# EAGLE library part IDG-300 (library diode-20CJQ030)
InvenSense's IDG-300 Integrated Dual-Axis Gyro Description: The IDG-300 is an integrated dual-axis angular rate sensor (gyroscope). It uses InvenSense?s proprietary and patented MEMS technology with vertically driven, vibrating masses to make a functionally complete, lowcost, dual-axis angular rate sensor. All required electronics are integrated onto a single chip with the sensor. The IDG-300 gyro uses two sensor elements with novel vibrating dual-mass bulk silicon configurations that sense the rate of rotation about the X- and Y-axis (in-plane sensing). This results in a unique, integrated dual-axis gyro with guaranteed-by-design vibration rejection and high cross-axis isolation. It is specifically designed for demanding consumer applications requiring low cost, small size and high performance. The IDG-300 gyro includes integrated electronics necessary for application-ready functionality. It incorporates X- and Y-axis low-pass filters and an EEPROM for on-chip factory calibration of the sensor. Factory trimmed scale factors eliminate the need for external active components and end-user calibration. This product is lead-free and Green Compliant. Features: Integrated X- and Y-axis gyro on a single chip Factory trimmed full scale range of ±500°/sec Integrated low-pass filters Superior vibration rejection over a wide frequency range High cross-axis isolation by design 3V single supply operation 5000 g shock tolerance RoHS compliant (completely lead free) 6 x 6 x 1.5mm QFN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
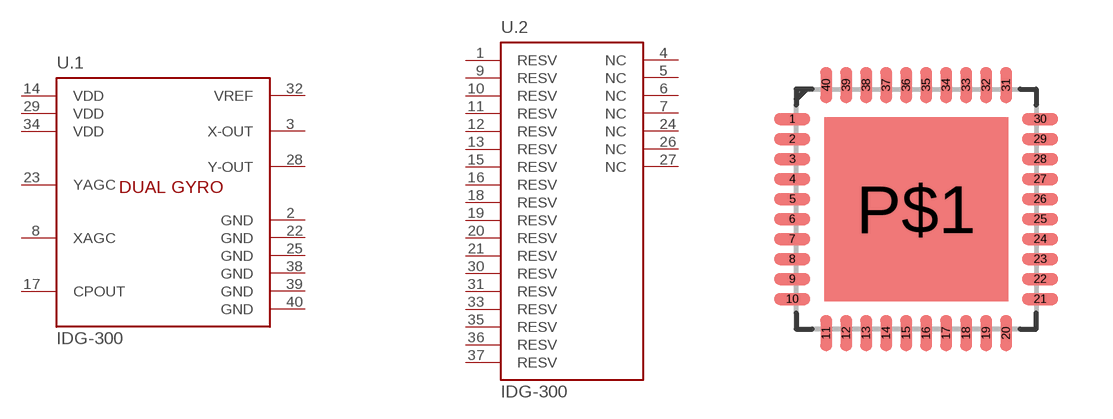
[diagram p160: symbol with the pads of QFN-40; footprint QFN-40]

Designator prefix U; gates .1=IDG-300 .2=IDG-300-NC

## IDG-300  [QFN-40]
1  .2:RESV  pas
2  .1:GND  pwr
3  .1:X-OUT  out
4  .2:NC  nc
5  .2:NC  nc
6  .2:NC  nc
7  .2:NC  nc
8  .1:XAGC  in
9  .2:RESV  pas
10  .2:RESV  pas
11  .2:RESV  pas
12  .2:RESV  pas
13  .2:RESV  pas
14  .1:VDD  pwr
15  .2:RESV  pas
16  .2:RESV  pas
17  .1:CPOUT  out
18  .2:RESV  pas
19  .2:RESV  pas
20  .2:RESV  pas
21  .2:RESV  pas
22  .1:GND  pwr
23  .1:YAGC  in
24  .2:NC  nc
25  .1:GND  pwr
26  .2:NC  nc
27  .2:NC  nc
28  .1:Y-OUT  out
29  .1:VDD  pwr
30  .2:RESV  pas
31  .2:RESV  pas
32  .1:VREF  in
33  .2:RESV  pas
34  .1:VDD  pwr
35  .2:RESV  pas
36  .2:RESV  pas
37  .2:RESV  pas
38  .1:GND  pwr
39  .1:GND  pwr
40  .1:GND  pwr

## Footprint QFN-40 (pad centres in mm)
QFN-40 package use in InvenSense IDG-300
smd 0.9 x 0.3: 1 -3.1,2.25; 2 -3.1,1.75; 3 -3.1,1.25; 4 -3.1,0.75; 5 -3.1,0.25; 6 -3.1,-0.25; 7 -3.1,-0.75; 8 -3.1,-1.25; 9 -3.1,-1.75; 10 -3.1,-2.25; 21 3.1,-2.25; 22 3.1,-1.75; 23 3.1,-1.25; 24 3.1,-0.75; 25 3.1,-0.25; 26 3.1,0.25; 27 3.1,0.75; 28 3.1,1.25; 29 3.1,1.75; 30 3.1,2.25
smd 0.3 x 0.9: 11 -2.25,-3.1; 12 -1.75,-3.1; 13 -1.25,-3.1; 14 -0.75,-3.1; 15 -0.25,-3.1; 16 0.25,-3.1; 17 0.75,-3.1; 18 1.25,-3.1; 19 1.75,-3.1; 20 2.25,-3.1; 31 2.25,3.1; 32 1.75,3.1; 33 1.25,3.1; 34 0.75,3.1; 35 0.25,3.1; 36 -0.25,3.1; 37 -0.75,3.1; 38 -1.25,3.1; 39 -1.75,3.1; 40 -2.25,3.1
smd 4.6 x 4.6: P$1 0,0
